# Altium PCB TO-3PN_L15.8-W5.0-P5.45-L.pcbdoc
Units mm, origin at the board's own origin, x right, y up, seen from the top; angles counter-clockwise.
Board outline 28.7 x 17.83 mm, 2 copper layers (Top Layer, Bottom Layer), stack 0 mm thick; 1 components, 0 nets, 3 pads, 0 vias.
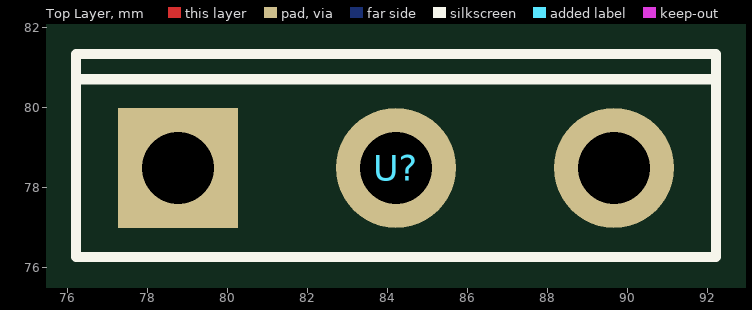
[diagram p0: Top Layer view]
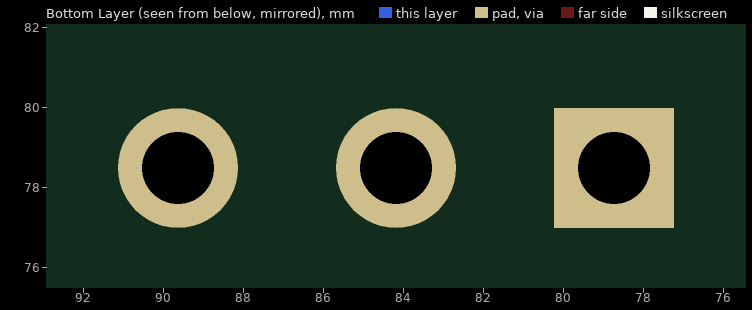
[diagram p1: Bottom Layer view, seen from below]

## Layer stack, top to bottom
Top Layer: signal copper (thickness not stored)
Bottom Layer: signal copper (thickness not stored)

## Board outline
98.551,69.85 69.85,69.85 69.85,87.678 98.551,87.678

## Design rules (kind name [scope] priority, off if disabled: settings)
PasteMaskExpansion "Paste Mask Expansion" [All] p1: expansion=0
SolderMaskExpansion "Solder Mask Expansion" [IsVia] p1: expansion=-25.4 istentingtop=TRUE
SolderMaskExpansion "Solder Mask Expansion" [All] p2: expansion=0.051 istentingtop=FALSE

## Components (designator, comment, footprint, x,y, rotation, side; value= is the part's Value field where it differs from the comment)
U? "" TO-3PN_L15.8-W5.0-P5.45-L 84.2,78.48 r0 top

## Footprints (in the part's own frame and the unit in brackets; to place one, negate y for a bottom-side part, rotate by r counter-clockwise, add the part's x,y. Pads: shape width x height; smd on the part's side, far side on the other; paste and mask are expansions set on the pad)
TO-3PN_L15.8-W5.0-P5.45-L [mm]
  rect 3x3 hole 1.8: 1(-5.451,0)
  round 3 hole 1.8: 2(0,0) 3(5.451,0)
  silkscreen extent -8,-2.23 8,2.85

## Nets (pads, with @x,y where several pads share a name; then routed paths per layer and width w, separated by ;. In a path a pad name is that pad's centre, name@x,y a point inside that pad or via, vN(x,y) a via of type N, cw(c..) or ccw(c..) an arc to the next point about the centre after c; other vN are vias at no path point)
pads on no net: U?.1 U?.2 U?.3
